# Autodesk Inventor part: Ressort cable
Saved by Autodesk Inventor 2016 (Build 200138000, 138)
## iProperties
Created: 2007-12
Part Number: Ressort cable
Material: solidworks materials|Acier allié (SS)
Document SubType Name: Modeling
Designer: Bruno
Density: 7.7 g/cm^3
Appearance: 165,158,150
Author: Bruno
Sending System: SolidWorks 2013
Last Author: christophe
Last Saved: 2014-02-15
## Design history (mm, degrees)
feature "Répétition circulaire1"
node "Solide1"
